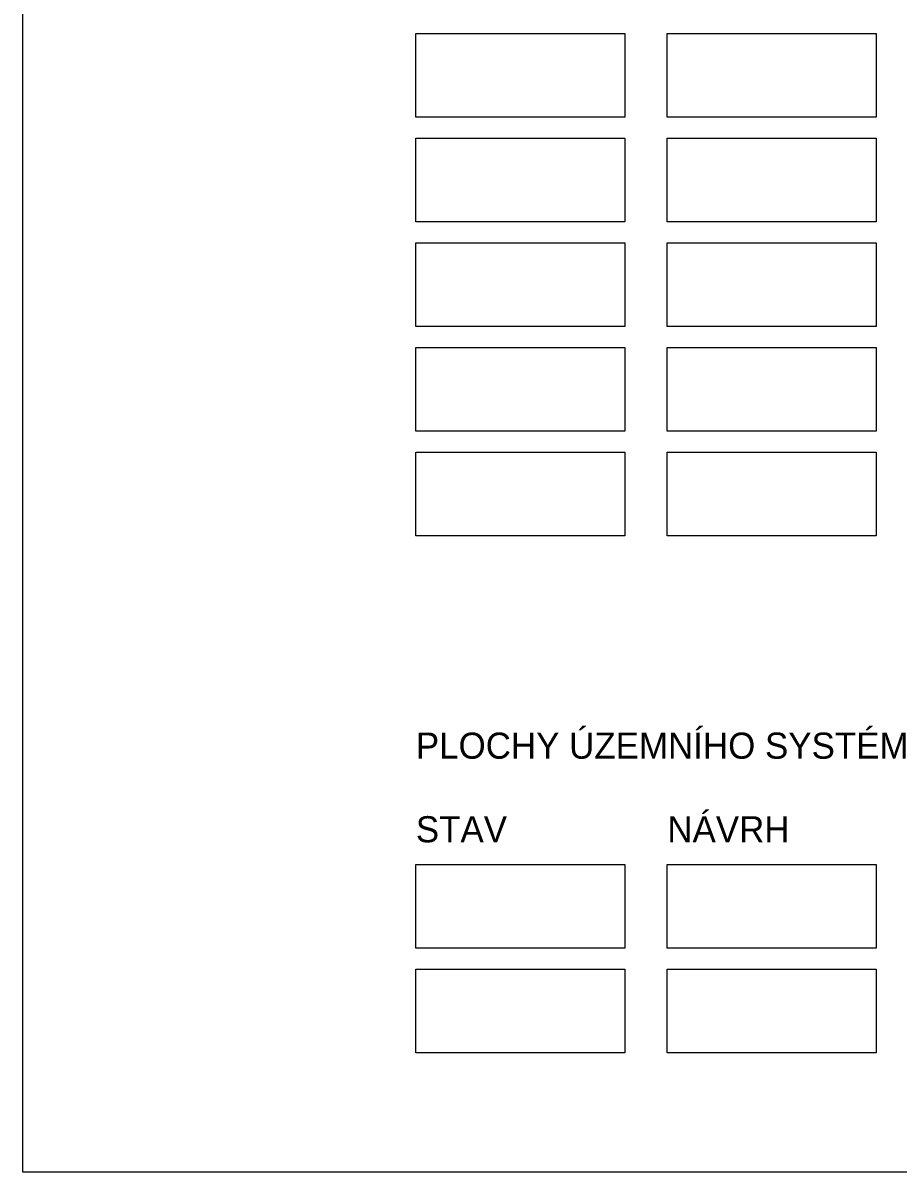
# Model space of a CAD drawing. Extents: x -443494 to -430443, y -1146902 to -1140081.
# Drawn here: x -440035 to -439599, y -1146894 to -1146323 of the extents above; entities that cross this region are included whole.
import ezdxf

# ---------------------------------------------------------------- set-up
doc = ezdxf.new("R2010")
doc.units = 0
doc.layers.add('Vrstva 1', color=7, linetype='Continuous')

msp = doc.modelspace()

# ---------------------------------------------------------------- linework, layer by layer
at = {"layer": 'Vrstva 1'}
for points in [[(-437534.759, -1144644.23), (-437534.759, -1146894.23), (-440034.759, -1146894.23), (-440034.759, -1144644.23)], [(-439839.168, -1146327.776), (-439735.168, -1146327.776), (-439735.168, -1146369.376), (-439839.168, -1146369.376)], [(-439839.168, -1146327.776), (-439735.168, -1146327.776), (-439735.168, -1146369.376), (-439839.168, -1146369.376)], [(-439839.168, -1146327.776), (-439735.168, -1146327.776), (-439735.168, -1146369.376), (-439839.168, -1146369.376)], [(-439839.168, -1146327.776), (-439735.168, -1146327.776), (-439735.168, -1146369.376), (-439839.168, -1146369.376)], [(-439839.168, -1146327.776), (-439735.168, -1146327.776), (-439735.168, -1146369.376), (-439839.168, -1146369.376)], [(-439839.168, -1146327.776), (-439735.168, -1146327.776), (-439735.168, -1146369.376), (-439839.168, -1146369.376)], [(-439839.168, -1146327.776), (-439735.168, -1146327.776), (-439735.168, -1146369.376), (-439839.168, -1146369.376)], [(-439839.168, -1146327.776), (-439735.168, -1146327.776), (-439735.168, -1146369.376), (-439839.168, -1146369.376)], [(-439713.976, -1146327.776), (-439609.976, -1146327.776), (-439609.976, -1146369.376), (-439713.976, -1146369.376)], [(-439713.976, -1146327.776), (-439609.976, -1146327.776), (-439609.976, -1146369.376), (-439713.976, -1146369.376)], [(-439713.976, -1146327.776), (-439609.976, -1146327.776), (-439609.976, -1146369.376), (-439713.976, -1146369.376)], [(-439713.976, -1146327.776), (-439609.976, -1146327.776), (-439609.976, -1146369.376), (-439713.976, -1146369.376)], [(-439713.976, -1146327.776), (-439609.976, -1146327.776), (-439609.976, -1146369.376), (-439713.976, -1146369.376)], [(-439713.976, -1146327.776), (-439609.976, -1146327.776), (-439609.976, -1146369.376), (-439713.976, -1146369.376)], [(-439713.976, -1146327.776), (-439609.976, -1146327.776), (-439609.976, -1146369.376), (-439713.976, -1146369.376)], [(-439713.976, -1146327.776), (-439609.976, -1146327.776), (-439609.976, -1146369.376), (-439713.976, -1146369.376)], [(-439839.168, -1146379.868), (-439735.168, -1146379.868), (-439735.168, -1146421.468), (-439839.168, -1146421.468)], [(-439839.168, -1146379.868), (-439735.168, -1146379.868), (-439735.168, -1146421.468), (-439839.168, -1146421.468)], [(-439839.168, -1146379.868), (-439735.168, -1146379.868), (-439735.168, -1146421.468), (-439839.168, -1146421.468)], [(-439839.168, -1146379.868), (-439735.168, -1146379.868), (-439735.168, -1146421.468), (-439839.168, -1146421.468)], [(-439839.168, -1146379.868), (-439735.168, -1146379.868), (-439735.168, -1146421.468), (-439839.168, -1146421.468)], [(-439839.168, -1146379.868), (-439735.168, -1146379.868), (-439735.168, -1146421.468), (-439839.168, -1146421.468)], [(-439839.168, -1146379.868), (-439735.168, -1146379.868), (-439735.168, -1146421.468), (-439839.168, -1146421.468)], [(-439839.168, -1146379.868), (-439735.168, -1146379.868), (-439735.168, -1146421.468), (-439839.168, -1146421.468)], [(-439713.976, -1146379.868), (-439609.976, -1146379.868), (-439609.976, -1146421.468), (-439713.976, -1146421.468)], [(-439713.976, -1146379.868), (-439609.976, -1146379.868), (-439609.976, -1146421.468), (-439713.976, -1146421.468)], [(-439713.976, -1146379.868), (-439609.976, -1146379.868), (-439609.976, -1146421.468), (-439713.976, -1146421.468)], [(-439713.976, -1146379.868), (-439609.976, -1146379.868), (-439609.976, -1146421.468), (-439713.976, -1146421.468)], [(-439713.976, -1146379.868), (-439609.976, -1146379.868), (-439609.976, -1146421.468), (-439713.976, -1146421.468)], [(-439713.976, -1146379.868), (-439609.976, -1146379.868), (-439609.976, -1146421.468), (-439713.976, -1146421.468)], [(-439713.976, -1146379.868), (-439609.976, -1146379.868), (-439609.976, -1146421.468), (-439713.976, -1146421.468)], [(-439713.976, -1146379.868), (-439609.976, -1146379.868), (-439609.976, -1146421.468), (-439713.976, -1146421.468)], [(-439839.168, -1146431.96), (-439735.168, -1146431.96), (-439735.168, -1146473.56), (-439839.168, -1146473.56)], [(-439839.168, -1146431.96), (-439735.168, -1146431.96), (-439735.168, -1146473.56), (-439839.168, -1146473.56)], [(-439839.168, -1146431.96), (-439735.168, -1146431.96), (-439735.168, -1146473.56), (-439839.168, -1146473.56)], [(-439839.168, -1146431.96), (-439735.168, -1146431.96), (-439735.168, -1146473.56), (-439839.168, -1146473.56)], [(-439839.168, -1146431.96), (-439735.168, -1146431.96), (-439735.168, -1146473.56), (-439839.168, -1146473.56)], [(-439839.168, -1146431.96), (-439735.168, -1146431.96), (-439735.168, -1146473.56), (-439839.168, -1146473.56)], [(-439839.168, -1146431.96), (-439735.168, -1146431.96), (-439735.168, -1146473.56), (-439839.168, -1146473.56)], [(-439839.168, -1146431.96), (-439735.168, -1146431.96), (-439735.168, -1146473.56), (-439839.168, -1146473.56)], [(-439713.976, -1146431.96), (-439609.976, -1146431.96), (-439609.976, -1146473.56), (-439713.976, -1146473.56)], [(-439713.976, -1146431.96), (-439609.976, -1146431.96), (-439609.976, -1146473.56), (-439713.976, -1146473.56)], [(-439713.976, -1146431.96), (-439609.976, -1146431.96), (-439609.976, -1146473.56), (-439713.976, -1146473.56)], [(-439713.976, -1146431.96), (-439609.976, -1146431.96), (-439609.976, -1146473.56), (-439713.976, -1146473.56)], [(-439713.976, -1146431.96), (-439609.976, -1146431.96), (-439609.976, -1146473.56), (-439713.976, -1146473.56)], [(-439713.976, -1146431.96), (-439609.976, -1146431.96), (-439609.976, -1146473.56), (-439713.976, -1146473.56)], [(-439713.976, -1146431.96), (-439609.976, -1146431.96), (-439609.976, -1146473.56), (-439713.976, -1146473.56)], [(-439713.976, -1146431.96), (-439609.976, -1146431.96), (-439609.976, -1146473.56), (-439713.976, -1146473.56)], [(-439839.168, -1146484.052), (-439735.168, -1146484.052), (-439735.168, -1146525.652), (-439839.168, -1146525.652)], [(-439839.168, -1146484.052), (-439735.168, -1146484.052), (-439735.168, -1146525.652), (-439839.168, -1146525.652)], [(-439839.168, -1146484.052), (-439735.168, -1146484.052), (-439735.168, -1146525.652), (-439839.168, -1146525.652)], [(-439839.168, -1146484.052), (-439735.168, -1146484.052), (-439735.168, -1146525.652), (-439839.168, -1146525.652)], [(-439839.168, -1146484.052), (-439735.168, -1146484.052), (-439735.168, -1146525.652), (-439839.168, -1146525.652)], [(-439839.168, -1146484.052), (-439735.168, -1146484.052), (-439735.168, -1146525.652), (-439839.168, -1146525.652)], [(-439839.168, -1146484.052), (-439735.168, -1146484.052), (-439735.168, -1146525.652), (-439839.168, -1146525.652)], [(-439839.168, -1146484.052), (-439735.168, -1146484.052), (-439735.168, -1146525.652), (-439839.168, -1146525.652)], [(-439713.976, -1146484.052), (-439609.976, -1146484.052), (-439609.976, -1146525.652), (-439713.976, -1146525.652)], [(-439713.976, -1146484.052), (-439609.976, -1146484.052), (-439609.976, -1146525.652), (-439713.976, -1146525.652)], [(-439713.976, -1146484.052), (-439609.976, -1146484.052), (-439609.976, -1146525.652), (-439713.976, -1146525.652)], [(-439713.976, -1146484.052), (-439609.976, -1146484.052), (-439609.976, -1146525.652), (-439713.976, -1146525.652)], [(-439713.976, -1146484.052), (-439609.976, -1146484.052), (-439609.976, -1146525.652), (-439713.976, -1146525.652)], [(-439713.976, -1146484.052), (-439609.976, -1146484.052), (-439609.976, -1146525.652), (-439713.976, -1146525.652)], [(-439713.976, -1146484.052), (-439609.976, -1146484.052), (-439609.976, -1146525.652), (-439713.976, -1146525.652)], [(-439713.976, -1146484.052), (-439609.976, -1146484.052), (-439609.976, -1146525.652), (-439713.976, -1146525.652)], [(-439839.168, -1146536.144), (-439735.168, -1146536.144), (-439735.168, -1146577.744), (-439839.168, -1146577.744)], [(-439839.168, -1146536.144), (-439735.168, -1146536.144), (-439735.168, -1146577.744), (-439839.168, -1146577.744)], [(-439839.168, -1146536.144), (-439735.168, -1146536.144), (-439735.168, -1146577.744), (-439839.168, -1146577.744)], [(-439839.168, -1146536.144), (-439735.168, -1146536.144), (-439735.168, -1146577.744), (-439839.168, -1146577.744)], [(-439839.168, -1146536.144), (-439735.168, -1146536.144), (-439735.168, -1146577.744), (-439839.168, -1146577.744)], [(-439839.168, -1146536.144), (-439735.168, -1146536.144), (-439735.168, -1146577.744), (-439839.168, -1146577.744)], [(-439839.168, -1146536.144), (-439735.168, -1146536.144), (-439735.168, -1146577.744), (-439839.168, -1146577.744)], [(-439839.168, -1146536.144), (-439735.168, -1146536.144), (-439735.168, -1146577.744), (-439839.168, -1146577.744)], [(-439713.976, -1146536.144), (-439609.976, -1146536.144), (-439609.976, -1146577.744), (-439713.976, -1146577.744)], [(-439713.976, -1146536.144), (-439609.976, -1146536.144), (-439609.976, -1146577.744), (-439713.976, -1146577.744)], [(-439713.976, -1146536.144), (-439609.976, -1146536.144), (-439609.976, -1146577.744), (-439713.976, -1146577.744)], [(-439713.976, -1146536.144), (-439609.976, -1146536.144), (-439609.976, -1146577.744), (-439713.976, -1146577.744)], [(-439713.976, -1146536.144), (-439609.976, -1146536.144), (-439609.976, -1146577.744), (-439713.976, -1146577.744)], [(-439713.976, -1146536.144), (-439609.976, -1146536.144), (-439609.976, -1146577.744), (-439713.976, -1146577.744)], [(-439713.976, -1146536.144), (-439609.976, -1146536.144), (-439609.976, -1146577.744), (-439713.976, -1146577.744)], [(-439713.976, -1146536.144), (-439609.976, -1146536.144), (-439609.976, -1146577.744), (-439713.976, -1146577.744)], [(-439839.168, -1146741.198), (-439735.168, -1146741.198), (-439735.168, -1146782.798), (-439839.168, -1146782.798)], [(-439839.168, -1146741.198), (-439735.168, -1146741.198), (-439735.168, -1146782.798), (-439839.168, -1146782.798)], [(-439839.168, -1146741.198), (-439735.168, -1146741.198), (-439735.168, -1146782.798), (-439839.168, -1146782.798)], [(-439839.168, -1146741.198), (-439735.168, -1146741.198), (-439735.168, -1146782.798), (-439839.168, -1146782.798)], [(-439713.976, -1146741.198), (-439609.976, -1146741.198), (-439609.976, -1146782.798), (-439713.976, -1146782.798)], [(-439713.976, -1146741.198), (-439609.976, -1146741.198), (-439609.976, -1146782.798), (-439713.976, -1146782.798)], [(-439713.976, -1146741.198), (-439609.976, -1146741.198), (-439609.976, -1146782.798), (-439713.976, -1146782.798)], [(-439713.976, -1146741.198), (-439609.976, -1146741.198), (-439609.976, -1146782.798), (-439713.976, -1146782.798)], [(-439839.168, -1146793.29), (-439735.168, -1146793.29), (-439735.168, -1146834.89), (-439839.168, -1146834.89)], [(-439839.168, -1146793.29), (-439735.168, -1146793.29), (-439735.168, -1146834.89), (-439839.168, -1146834.89)], [(-439839.168, -1146793.29), (-439735.168, -1146793.29), (-439735.168, -1146834.89), (-439839.168, -1146834.89)], [(-439839.168, -1146793.29), (-439735.168, -1146793.29), (-439735.168, -1146834.89), (-439839.168, -1146834.89)], [(-439713.976, -1146793.29), (-439609.976, -1146793.29), (-439609.976, -1146834.89), (-439713.976, -1146834.89)], [(-439713.976, -1146793.29), (-439609.976, -1146793.29), (-439609.976, -1146834.89), (-439713.976, -1146834.89)], [(-439713.976, -1146793.29), (-439609.976, -1146793.29), (-439609.976, -1146834.89), (-439713.976, -1146834.89)], [(-439713.976, -1146793.29), (-439609.976, -1146793.29), (-439609.976, -1146834.89), (-439713.976, -1146834.89)]]:
    msp.add_lwpolyline(points, close=True, dxfattribs=at)

# ---------------------------------------------------------------- texts
for s, p in [('PLOCHY ÚZEMNÍHO SYSTÉMU EKOLOGICKÉ STABILITY - ÚSES', (-439839.168, -1146688.586)), ('NÁVRH', (-439713.976, -1146730.186)), ('NÁVRH', (-439713.976, -1146730.186)), ('NÁVRH', (-439713.976, -1146730.186)), ('NÁVRH', (-439713.976, -1146730.186)), ('STAV', (-439839.168, -1146730.186)), ('STAV', (-439839.168, -1146730.186)), ('STAV', (-439839.168, -1146730.186)), ('STAV', (-439839.168, -1146730.186))]:
    msp.add_text(s, height=12.9974, dxfattribs=at).set_placement(p)

doc.saveas('drawing.dxf')
